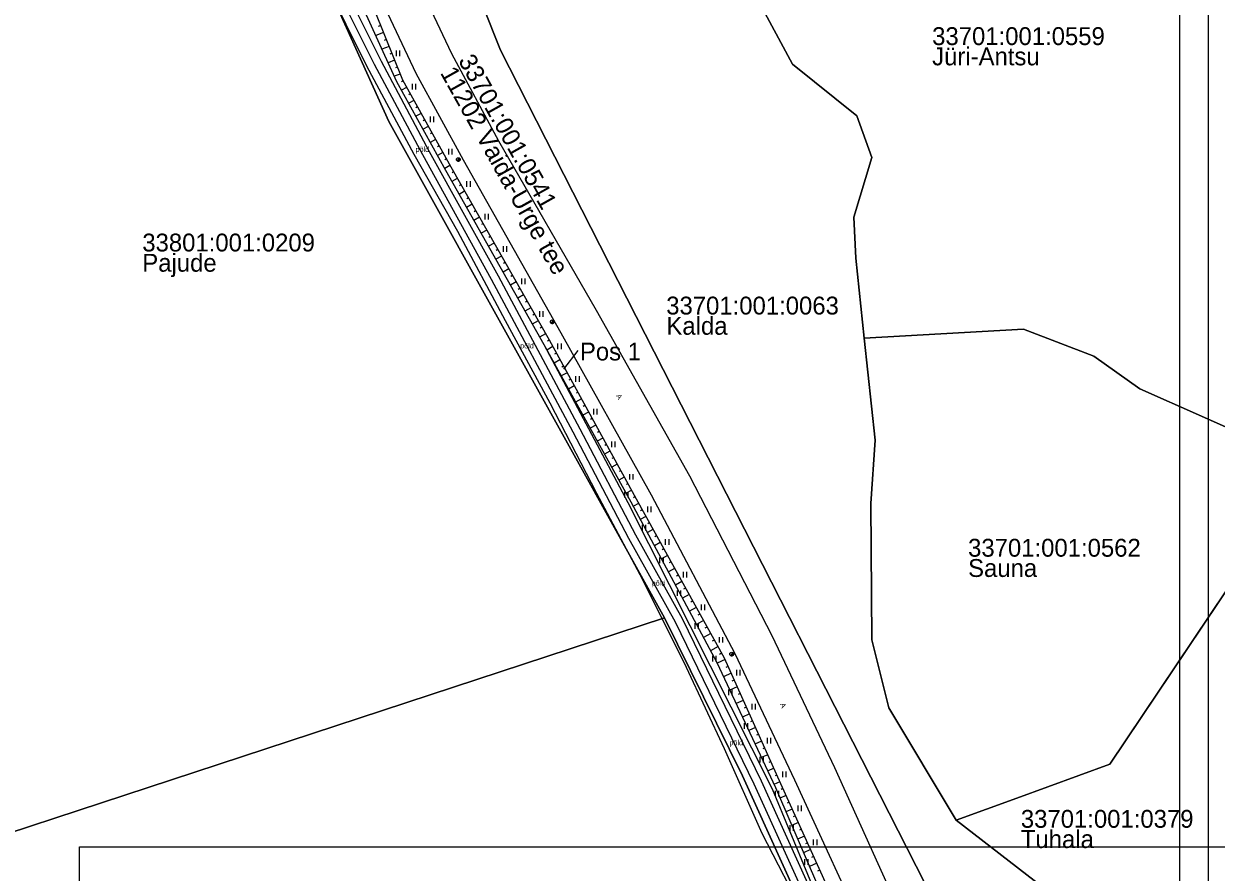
# Model space of a CAD drawing. Extents: x 554947 to 555436, y 6564938 to 6565792.
# Drawn here: x 555027.7 to 555187.9, y 6565441.5 to 6565555.5 of the extents above; entities that cross this region are included whole.
import ezdxf

# ---------------------------------------------------------------- set-up
doc = ezdxf.new("R2010")
doc.units = 0
for name, color, linetype in [('HALJASTUS', 7, 'Continuous'), ('KASUTUSALA', 7, 'Continuous'), ('KPKAABEL', 7, 'Continuous'), ('PIIR', 7, 'Continuous'), ('POST', 7, 'Continuous'), ('PR_SIDE', 7, 'Continuous'), ('RELJEEF', 7, 'Continuous'), ('TEE', 7, 'Continuous'), ('VORMISTUS_1', 7, 'Continuous'), ('VORMISTUS_2', 7, 'Continuous'), ('VORMISTUS_3', 7, 'Continuous')]:
    doc.layers.add(name, color=color, linetype=linetype)

msp = doc.modelspace()

# ---------------------------------------------------------------- linework, layer by layer
at = {"layer": 'HALJASTUS'}
for p, q in [((555077.72, 6565551.92), (555077.72, 6565551.16)), ((555078.18, 6565551.92), (555078.18, 6565551.16)), ((555079.87, 6565547.41), (555079.87, 6565546.65)), ((555080.32, 6565547.41), (555080.32, 6565546.65)), ((555082.32, 6565543.05), (555082.32, 6565542.29)), ((555082.77, 6565543.05), (555082.77, 6565542.29)), ((555084.77, 6565538.69), (555084.77, 6565537.93)), ((555085.22, 6565538.69), (555085.22, 6565537.93)), ((555087.21, 6565534.33), (555087.21, 6565533.57)), ((555087.67, 6565534.33), (555087.67, 6565533.57)), ((555089.66, 6565529.97), (555089.66, 6565529.21)), ((555090.12, 6565529.97), (555090.12, 6565529.21)), ((555092.11, 6565525.61), (555092.11, 6565524.85)), ((555092.57, 6565525.61), (555092.57, 6565524.85)), ((555094.56, 6565521.25), (555094.56, 6565520.49)), ((555095.01, 6565521.25), (555095.01, 6565520.49)), ((555097.01, 6565516.89), (555097.01, 6565516.13)), ((555097.46, 6565516.89), (555097.46, 6565516.13)), ((555099.44, 6565512.53), (555099.44, 6565511.76)), ((555099.9, 6565512.53), (555099.9, 6565511.76)), ((555101.85, 6565508.14), (555101.85, 6565507.38)), ((555102.31, 6565508.14), (555102.31, 6565507.38)), ((555104.27, 6565503.76), (555104.27, 6565503)), ((555104.72, 6565503.76), (555104.72, 6565503)), ((555106.68, 6565499.38), (555106.68, 6565498.62)), ((555107.13, 6565499.38), (555107.13, 6565498.62)), ((555109.09, 6565495), (555109.09, 6565494.24)), ((555109.54, 6565495), (555109.54, 6565494.24)), ((555108.42, 6565492.59), (555108.42, 6565491.83)), ((555108.87, 6565492.59), (555108.87, 6565491.83)), ((555111.5, 6565490.62), (555111.5, 6565489.86)), ((555111.95, 6565490.62), (555111.95, 6565489.86)), ((555110.78, 6565488.19), (555110.78, 6565487.43)), ((555111.24, 6565488.19), (555111.24, 6565487.43)), ((555113.91, 6565486.24), (555113.91, 6565485.48)), ((555114.36, 6565486.24), (555114.36, 6565485.48)), ((555113.14, 6565483.78), (555113.14, 6565483.02)), ((555113.6, 6565483.78), (555113.6, 6565483.02)), ((555116.32, 6565481.86), (555116.32, 6565481.1)), ((555116.77, 6565481.86), (555116.77, 6565481.1)), ((555115.51, 6565479.37), (555115.51, 6565478.61)), ((555115.96, 6565479.37), (555115.96, 6565478.61)), ((555118.73, 6565477.48), (555118.73, 6565476.72)), ((555119.18, 6565477.48), (555119.18, 6565476.72)), ((555117.87, 6565474.97), (555117.87, 6565474.21)), ((555118.32, 6565474.97), (555118.32, 6565474.21)), ((555121.14, 6565473.1), (555121.14, 6565472.34)), ((555121.6, 6565473.1), (555121.6, 6565472.34)), ((555120.23, 6565470.56), (555120.23, 6565469.8)), ((555120.69, 6565470.56), (555120.69, 6565469.8)), ((555123.46, 6565468.68), (555123.46, 6565467.92)), ((555123.92, 6565468.68), (555123.92, 6565467.92)), ((555122.38, 6565466.05), (555122.38, 6565465.28)), ((555122.83, 6565466.05), (555122.83, 6565465.28)), ((555125.53, 6565464.12), (555125.53, 6565463.36)), ((555125.98, 6565464.12), (555125.98, 6565463.36)), ((555124.5, 6565461.52), (555124.5, 6565460.76)), ((555124.95, 6565461.52), (555124.95, 6565460.76)), ((555127.59, 6565459.57), (555127.59, 6565458.81)), ((555128.05, 6565459.57), (555128.05, 6565458.81)), ((555126.61, 6565456.99), (555126.61, 6565456.23)), ((555127.07, 6565456.99), (555127.07, 6565456.23)), ((555129.66, 6565455.02), (555129.66, 6565454.26)), ((555130.12, 6565455.02), (555130.12, 6565454.26)), ((555128.68, 6565452.44), (555128.68, 6565451.67)), ((555129.14, 6565452.44), (555129.14, 6565451.67)), ((555131.73, 6565450.46), (555131.73, 6565449.7)), ((555132.18, 6565450.46), (555132.18, 6565449.7)), ((555130.64, 6565447.83), (555130.64, 6565447.07)), ((555131.09, 6565447.83), (555131.09, 6565447.07)), ((555133.79, 6565445.91), (555133.79, 6565445.15)), ((555134.25, 6565445.91), (555134.25, 6565445.15)), ((555132.6, 6565443.23), (555132.6, 6565442.47)), ((555133.05, 6565443.23), (555133.05, 6565442.47))]:
    msp.add_line(p, q, dxfattribs=at)
msp.add_lwpolyline([(555097.58, 6565512.39), (555108.86, 6565491.15), (555128.28, 6565452.72), (555137.76, 6565429.75), (555137.45, 6565422.91)], dxfattribs=at)
at = {"layer": 'KASUTUSALA'}
msp.add_lwpolyline([(555144.16, 6565410.6), (555124.27, 6565454.45), (555113.82, 6565475.68), (555076.76, 6565542.38), (555065.78, 6565566.7), (555060.42, 6565583.26), (555057.95, 6565596.72), (555059.66, 6565595.65), (555060.33, 6565594.85), (555062.36, 6565583.75), (555067.55, 6565567.72), (555071.2, 6565559.54), (555075.7, 6565550.48), (555082.19, 6565538.35), (555091.44, 6565521.62), (555102.43, 6565501.09), (555109.9, 6565486.83), (555116.17, 6565475.57), (555126.77, 6565453.77), (555135.2, 6565435.2)], dxfattribs=at)
at = {"layer": 'KPKAABEL'}
msp.add_lwpolyline([(555022.08, 6565654.91), (555021.62, 6565652.63), (555021.53, 6565649.77), (555022.79, 6565647.23), (555026.48, 6565641.46), (555030.61, 6565629.73), (555035.38, 6565618.81), (555040.84, 6565608.06), (555047.09, 6565597.8), (555053.57, 6565587.29), (555056.07, 6565583.7), (555062.11, 6565572.67), (555068.25, 6565560.98), (555073.77, 6565549.85), (555080.11, 6565537.98), (555085.96, 6565527.61), (555092.4, 6565515.61), (555098.4, 6565504.54), (555104.64, 6565492.44), (555110.84, 6565480.82), (555116.7, 6565469.07), (555121.82, 6565458.12), (555126.89, 6565446.73), (555132.74, 6565435.39)], dxfattribs=at)
at = {"layer": 'PIIR'}
for points in [[(555016.05, 6565654.91), (555030.24, 6565648.23), (555043.11, 6565640.11), (555053.62, 6565632.14), (555056.61, 6565622.91), (555057.22, 6565600.73), (555060.42, 6565583.26), (555065.78, 6565566.7), (555076.76, 6565542.38), (555113.82, 6565475.68), (554946.63, 6565420.78), (554981.01, 6565316.76), (555160.07, 6565375.54), (555166.64, 6565360.5), (555167.67, 6565357.91)], [(555144.16, 6565410.6), (555124.27, 6565454.45), (555113.82, 6565475.68), (555076.76, 6565542.38), (555065.78, 6565566.7), (555060.42, 6565583.26), (555057.22, 6565600.73), (555056.61, 6565622.91), (555063.43, 6565647.29), (555114.24, 6565634), (555129.77, 6565611.2), (555130.73, 6565621.32), (555138.66, 6565615.26), (555160.12, 6565598.86), (555193.24, 6565604.68), (555193.7, 6565602.7), (555225.47, 6565605.89), (555234.35, 6565605.6), (555251.24, 6565598.48), (555330.71, 6565538.85), (555343.81, 6565536.56), (555350.68, 6565540.44), (555361.56, 6565549.57), (555393.07, 6565582.1)], [(555171.91, 6565394.64), (555091.74, 6565551.94), (555075.34, 6565593.24), (555074.13, 6565607.82), (555079.04, 6565618.4), (555093.56, 6565628.47), (555109.96, 6565624.83), (555116.17, 6565610.5), (555099.5, 6565594.91), (555105.26, 6565587.71), (555119.63, 6565564.84), (555126.35, 6565558.74), (555131.01, 6565550.06), (555139.64, 6565543.1), (555141.68, 6565537.52), (555139.26, 6565529.51), (555139.49, 6565523.98), (555140.65, 6565513.25), (555142.13, 6565499.56), (555141.53, 6565491.02), (555141.65, 6565472.71), (555143.93, 6565463.6), (555153.01, 6565448.47), (555207.22, 6565406.57)], [(555393.07, 6565560.97), (555353.12, 6565523.87), (555343.14, 6565512.46), (555302.6, 6565539.71), (555242.37, 6565583.94), (555179.42, 6565586.32), (555138.98, 6565580.6), (555121.18, 6565602.26), (555116.17, 6565610.5), (555109.96, 6565624.83), (555093.56, 6565628.47), (555079.04, 6565618.4), (555074.13, 6565607.82), (555075.34, 6565593.24), (555091.74, 6565551.94), (555171.91, 6565394.64), (555191.35, 6565341.19), (555195.08, 6565294.61), (555195.28, 6565271.63), (555191.64, 6565237.48)]]:
    msp.add_lwpolyline(points, dxfattribs=at)
for points in [[(555121.18, 6565602.26), (555138.98, 6565580.6), (555179.42, 6565586.32), (555242.37, 6565583.94), (555302.6, 6565539.71), (555287.77, 6565518.56), (555207.29, 6565506.14), (555200.64, 6565496.23), (555185.97, 6565502.75), (555177.68, 6565506.44), (555171.49, 6565510.85), (555162.05, 6565514.45), (555140.65, 6565513.25), (555139.49, 6565523.98), (555139.26, 6565529.51), (555141.68, 6565537.52), (555139.64, 6565543.1), (555131.01, 6565550.06), (555126.35, 6565558.74), (555119.63, 6565564.84), (555105.26, 6565587.71), (555099.5, 6565594.91), (555116.17, 6565610.5)], [(555153.01, 6565448.47), (555161.15, 6565451.45), (555173.66, 6565456.03), (555207.29, 6565506.14), (555287.77, 6565518.56), (555302.6, 6565539.71), (555343.14, 6565512.46), (555319.44, 6565481.04), (555323.07, 6565461.26), (555312.9, 6565433.84), (555316.84, 6565372.52), (555318.72, 6565342.57), (555320.51, 6565314.61), (555303.13, 6565302.54), (555208.78, 6565303.3), (555205.15, 6565297.11), (555200.72, 6565310.3), (555206.9, 6565339.44), (555221.23, 6565376.06), (555216.83, 6565392.35), (555207.22, 6565406.57)], [(555140.65, 6565513.25), (555162.05, 6565514.45), (555171.49, 6565510.85), (555177.68, 6565506.44), (555185.97, 6565502.75), (555200.64, 6565496.23), (555173.66, 6565456.03), (555161.15, 6565451.45), (555153.01, 6565448.47), (555143.93, 6565463.6), (555141.65, 6565472.71), (555141.53, 6565491.02), (555142.13, 6565499.56)], [(554981.01, 6565316.76), (554946.63, 6565420.78), (555113.82, 6565475.68), (555124.27, 6565454.45), (555144.16, 6565410.6), (555160.07, 6565375.54)]]:
    msp.add_lwpolyline(points, close=True, dxfattribs=at)
at = {"layer": 'POST'}
for p, q in [((555085.91, 6565537.07), (555086.26, 6565537.43)), ((555098.55, 6565515.27), (555098.9, 6565515.62)), ((555122.66, 6565470.63), (555123.01, 6565470.98))]:
    msp.add_line(p, q, dxfattribs=at)
for centre in [(555086.09, 6565537.25), (555098.72, 6565515.45), (555122.83, 6565470.81)]:
    msp.add_circle(centre, 0.25, dxfattribs=at)
for centre, radius, start, end in [((555086.09, 6565537.25), 0.225, 224.8541, 45.0356), ((555086.09, 6565537.25), 0.2, 224.8427, 45.047), ((555086.09, 6565537.25), 0.175, 224.8281, 45.0616), ((555086.09, 6565537.25), 0.15, 224.8087, 45.081), ((555086.09, 6565537.25), 0.125, 224.7814, 45.1083), ((555086.09, 6565537.25), 0.1, 224.7406, 45.1491), ((555086.09, 6565537.25), 0.075, 224.6725, 45.2172), ((555086.09, 6565537.25), 0.05, 224.5363, 45.3534), ((555086.09, 6565537.25), 0.025, 224.1278, 45.7619), ((555098.72, 6565515.45), 0.225, 224.8541, 45.0356), ((555098.72, 6565515.45), 0.2, 224.8427, 45.047), ((555098.72, 6565515.45), 0.175, 224.8281, 45.0616), ((555098.72, 6565515.45), 0.15, 224.8087, 45.081), ((555098.72, 6565515.45), 0.125, 224.7814, 45.1083), ((555098.72, 6565515.45), 0.1, 224.7406, 45.1491), ((555098.72, 6565515.45), 0.075, 224.6725, 45.2172), ((555098.72, 6565515.45), 0.05, 224.5363, 45.3534), ((555098.72, 6565515.45), 0.025, 224.1278, 45.7619), ((555122.83, 6565470.81), 0.225, 224.8541, 45.0356), ((555122.83, 6565470.81), 0.2, 224.8427, 45.047), ((555122.83, 6565470.81), 0.175, 224.8281, 45.0616), ((555122.83, 6565470.81), 0.15, 224.8087, 45.081), ((555122.83, 6565470.81), 0.125, 224.7814, 45.1083), ((555122.83, 6565470.81), 0.1, 224.7406, 45.1491), ((555122.83, 6565470.81), 0.075, 224.6725, 45.2172), ((555122.83, 6565470.81), 0.05, 224.5363, 45.3534), ((555122.83, 6565470.81), 0.025, 224.1278, 45.7619)]:
    msp.add_arc(centre, radius, start, end, dxfattribs=at)
at = {"layer": 'PR_SIDE'}
msp.add_lwpolyline([(555134.29, 6565434.78), (555125.87, 6565453.35), (555115.28, 6565475.11), (555109.02, 6565486.35), (555101.54, 6565500.63), (555090.56, 6565521.15), (555081.31, 6565537.88), (555074.81, 6565550.02), (555070.29, 6565559.11)], dxfattribs=at)
at = {"layer": 'RELJEEF'}
for p, q in [((555076.04, 6565554.31), (555075, 6565553.9)), ((555075.66, 6565555.24), (555075.34, 6565555.11)), ((555076.41, 6565553.38), (555076.11, 6565553.26)), ((555076.78, 6565552.45), (555075.83, 6565552.08)), ((555077.15, 6565551.53), (555076.88, 6565551.42)), ((555077.52, 6565550.6), (555076.66, 6565550.25)), ((555077.89, 6565549.67), (555077.65, 6565549.57)), ((555078.27, 6565548.74), (555077.49, 6565548.43)), ((555078.66, 6565547.82), (555078.45, 6565547.71)), ((555079.14, 6565546.95), (555078.45, 6565546.57)), ((555079.63, 6565546.07), (555079.42, 6565545.96)), ((555080.11, 6565545.2), (555079.42, 6565544.81)), ((555080.6, 6565544.33), (555080.39, 6565544.21)), ((555081.08, 6565543.45), (555080.39, 6565543.06)), ((555082.05, 6565541.7), (555081.35, 6565541.31)), ((555081.57, 6565542.58), (555081.36, 6565542.46)), ((555083.02, 6565539.95), (555082.32, 6565539.56)), ((555082.54, 6565540.83), (555082.33, 6565540.71)), ((555083.51, 6565539.08), (555083.3, 6565538.96)), ((555084, 6565538.2), (555083.29, 6565537.81)), ((555084.48, 6565537.33), (555084.27, 6565537.21)), ((555084.97, 6565536.46), (555084.26, 6565536.06)), ((555085.46, 6565535.59), (555085.25, 6565535.46)), ((555085.95, 6565534.72), (555085.24, 6565534.31)), ((555086.45, 6565533.85), (555086.23, 6565533.72)), ((555086.94, 6565532.98), (555086.22, 6565532.57)), ((555087.44, 6565532.11), (555087.22, 6565531.98)), ((555087.93, 6565531.24), (555087.2, 6565530.82)), ((555088.42, 6565530.37), (555088.2, 6565530.24)), ((555088.92, 6565529.5), (555088.18, 6565529.08)), ((555089.91, 6565527.76), (555089.16, 6565527.34)), ((555089.41, 6565528.63), (555089.19, 6565528.51)), ((555090.9, 6565526.02), (555090.14, 6565525.6)), ((555090.4, 6565526.89), (555090.18, 6565526.77)), ((555091.88, 6565524.29), (555091.13, 6565523.85)), ((555091.39, 6565525.15), (555091.16, 6565525.03)), ((555092.87, 6565522.55), (555092.11, 6565522.11)), ((555092.38, 6565523.42), (555092.15, 6565523.29)), ((555093.86, 6565520.81), (555093.09, 6565520.37)), ((555093.37, 6565521.68), (555093.14, 6565521.55)), ((555094.85, 6565519.07), (555094.07, 6565518.62)), ((555094.36, 6565519.94), (555094.12, 6565519.81)), ((555095.35, 6565518.2), (555095.11, 6565518.07)), ((555095.84, 6565517.33), (555095.05, 6565516.88)), ((555096.33, 6565516.46), (555096.1, 6565516.33)), ((555096.83, 6565515.59), (555096.03, 6565515.14)), ((555097.32, 6565514.72), (555097.08, 6565514.59)), ((555097.82, 6565513.85), (555097.01, 6565513.4)), ((555098.31, 6565512.98), (555098.07, 6565512.85)), ((555098.79, 6565512.11), (555097.98, 6565511.66)), ((555099.27, 6565511.23), (555099.03, 6565511.1)), ((555099.75, 6565510.35), (555098.95, 6565509.91)), ((555100.23, 6565509.47), (555099.99, 6565509.34)), ((555100.71, 6565508.6), (555099.92, 6565508.17)), ((555101.67, 6565506.84), (555100.89, 6565506.42)), ((555101.19, 6565507.72), (555100.95, 6565507.59)), ((555102.63, 6565505.09), (555101.86, 6565504.67)), ((555102.15, 6565505.96), (555101.92, 6565505.84)), ((555103.59, 6565503.33), (555102.83, 6565502.92)), ((555103.11, 6565504.21), (555102.88, 6565504.08)), ((555104.55, 6565501.58), (555103.8, 6565501.17)), ((555104.07, 6565502.46), (555103.84, 6565502.33)), ((555105.51, 6565499.82), (555104.77, 6565499.42)), ((555105.03, 6565500.7), (555104.8, 6565500.58)), ((555105.99, 6565498.95), (555105.77, 6565498.83)), ((555106.47, 6565498.07), (555105.74, 6565497.67)), ((555106.95, 6565497.19), (555106.73, 6565497.07)), ((555107.43, 6565496.31), (555106.71, 6565495.92)), ((555107.91, 6565495.44), (555107.69, 6565495.32)), ((555108.38, 6565494.56), (555107.68, 6565494.17)), ((555108.86, 6565493.68), (555108.65, 6565493.57)), ((555109.34, 6565492.8), (555108.65, 6565492.42)), ((555109.82, 6565491.93), (555109.62, 6565491.81)), ((555110.31, 6565491.05), (555109.61, 6565490.66)), ((555111.28, 6565489.3), (555110.55, 6565488.9)), ((555110.79, 6565490.18), (555110.58, 6565490.06)), ((555112.25, 6565487.55), (555111.5, 6565487.14)), ((555111.76, 6565488.43), (555111.54, 6565488.3)), ((555113.22, 6565485.81), (555112.44, 6565485.37)), ((555112.73, 6565486.68), (555112.5, 6565486.55)), ((555114.19, 6565484.06), (555113.38, 6565483.61)), ((555113.71, 6565484.93), (555113.47, 6565484.8)), ((555115.16, 6565482.31), (555114.33, 6565481.84)), ((555114.68, 6565483.18), (555114.43, 6565483.05)), ((555115.65, 6565481.43), (555115.39, 6565481.29)), ((555116.13, 6565480.56), (555115.27, 6565480.08)), ((555116.62, 6565479.68), (555116.35, 6565479.54)), ((555117.1, 6565478.81), (555116.21, 6565478.32)), ((555117.59, 6565477.94), (555117.32, 6565477.79)), ((555118.07, 6565477.06), (555117.15, 6565476.55)), ((555118.56, 6565476.19), (555118.28, 6565476.03)), ((555119.04, 6565475.31), (555118.1, 6565474.79)), ((555119.53, 6565474.44), (555119.24, 6565474.28)), ((555120.02, 6565473.56), (555119.04, 6565473.02)), ((555120.5, 6565472.69), (555120.2, 6565472.53)), ((555120.99, 6565471.82), (555119.98, 6565471.26)), ((555121.93, 6565470.06), (555120.87, 6565469.58)), ((555121.47, 6565470.94), (555121.17, 6565470.77)), ((555122.75, 6565468.23), (555121.72, 6565467.77)), ((555122.34, 6565469.14), (555122.03, 6565469)), ((555123.57, 6565466.41), (555122.57, 6565465.96)), ((555123.16, 6565467.32), (555122.86, 6565467.18)), ((555124.39, 6565464.58), (555123.42, 6565464.15)), ((555123.98, 6565465.5), (555123.69, 6565465.36)), ((555124.8, 6565463.67), (555124.52, 6565463.54)), ((555125.21, 6565462.76), (555124.27, 6565462.33)), ((555125.62, 6565461.85), (555125.34, 6565461.72)), ((555126.03, 6565460.94), (555125.11, 6565460.52)), ((555126.44, 6565460.02), (555126.17, 6565459.9)), ((555126.85, 6565459.11), (555125.96, 6565458.71)), ((555127.26, 6565458.2), (555127, 6565458.08)), ((555127.67, 6565457.29), (555126.81, 6565456.9)), ((555128.49, 6565455.46), (555127.66, 6565455.09)), ((555128.08, 6565456.37), (555127.83, 6565456.26)), ((555129.31, 6565453.64), (555128.51, 6565453.28)), ((555128.9, 6565454.55), (555128.66, 6565454.44)), ((555130.14, 6565451.82), (555129.31, 6565451.44)), ((555129.72, 6565452.73), (555129.48, 6565452.62)), ((555130.55, 6565450.9), (555130.3, 6565450.79)), ((555130.96, 6565449.99), (555130.1, 6565449.61)), ((555131.37, 6565449.08), (555131.11, 6565448.96)), ((555131.78, 6565448.17), (555130.9, 6565447.77)), ((555132.2, 6565447.26), (555131.92, 6565447.14)), ((555132.61, 6565446.35), (555131.69, 6565445.93)), ((555133.02, 6565445.44), (555132.74, 6565445.31)), ((555133.43, 6565444.53), (555132.48, 6565444.09)), ((555134.26, 6565442.7), (555133.27, 6565442.26)), ((555133.84, 6565443.62), (555133.55, 6565443.48)), ((555134.67, 6565441.79), (555134.37, 6565441.66))]:
    msp.add_line(p, q, dxfattribs=at)
for points in [[(555061.19, 6565603.86), (555063.02, 6565596.51), (555064.38, 6565585.09), (555067.44, 6565575.67), (555073.66, 6565560.25), (555078.57, 6565547.98), (555085.07, 6565536.27), (555098.29, 6565513.03), (555109.98, 6565491.65), (555121.81, 6565470.32), (555129.41, 6565453.42), (555139.71, 6565430.65), (555142.38, 6565424.28), (555142.55, 6565422.18)], [(555061.19, 6565603.86), (555061.85, 6565596.37), (555062.87, 6565584.51), (555066.18, 6565575.08), (555072.1, 6565560.27), (555077.8, 6565547.74), (555084.38, 6565535.83), (555097.58, 6565512.39), (555109.29, 6565491.27), (555120.83, 6565469.69), (555128.7, 6565452.87), (555138.48, 6565430.17), (555141.35, 6565423.96), (555142.55, 6565422.18)]]:
    msp.add_lwpolyline(points, dxfattribs=at)
at = {"layer": 'TEE'}
for points in [[(555063.04, 6565604.03), (555063.89, 6565596.59), (555066.15, 6565585.55), (555068.84, 6565576.18), (555074.68, 6565560.94), (555080.39, 6565548.87), (555086.72, 6565537.19), (555099.86, 6565513.95), (555112, 6565492.2), (555123.27, 6565470.87), (555131.27, 6565453.89), (555141.63, 6565431.43)], [(555146.7, 6565433.42), (555136.69, 6565455.53), (555128.27, 6565473.28), (555117.19, 6565494.73), (555104.65, 6565516.95), (555091.54, 6565539.74), (555085.22, 6565551.47), (555079.65, 6565563.24), (555074, 6565577.71), (555071.34, 6565586.86), (555069.39, 6565597.54), (555068.63, 6565604.43)]]:
    msp.add_lwpolyline(points, dxfattribs=at)
at = {"layer": 'VORMISTUS_1'}
msp.add_lwpolyline([(555035.19, 6565444.91), (555245.19, 6565444.91), (555245.19, 6565147.91), (555035.19, 6565147.91)], close=True, dxfattribs=at)
at = {"layer": 'VORMISTUS_2'}
msp.add_line((555100.25, 6565509.08), (555102.2, 6565511.58), dxfattribs=at)
msp.add_lwpolyline([(555186.86, 6565394.91), (555021.86, 6565394.91), (555021.86, 6565604.91), (555186.86, 6565604.91)], close=True, dxfattribs=at)
at = {"layer": 'VORMISTUS_3'}
msp.add_lwpolyline([(555183.07, 6565701.75), (555393.07, 6565701.75), (555393.07, 6565404.75), (555183.07, 6565404.75)], close=True, dxfattribs=at)

# ---------------------------------------------------------------- texts
at = {"layer": 'HALJASTUS'}
for p in [(555080.34, 6565538.27), (555094.4, 6565511.88), (555112.08, 6565479.98), (555122.52, 6565458.55)]:
    msp.add_text('põld', height=0.7, rotation=359.9544, dxfattribs=at).set_placement(p)
at = {"layer": 'PIIR'}
for s, p in [('33701:001:0559', (555149.77, 6565552.63)), ('Jüri-Antsu', (555149.77, 6565549.91)), ('33801:001:0209', (555043.62, 6565524.9)), ('Pajude', (555043.62, 6565522.18)), ('33701:001:0063', (555114.03, 6565516.43)), ('Kalda', (555114.06, 6565513.71)), ('33701:001:0562', (555154.6, 6565483.89)), ('Sauna', (555154.6, 6565481.17)), ('33701:001:0379', (555161.69, 6565447.47)), ('Tuhala', (555161.69, 6565444.75))]:
    msp.add_text(s, height=2.4, dxfattribs=at).set_placement(p)
for s, p in [('33701:001:0541', (555086.02, 6565550.55)), ('11202 Vaida-Urge tee', (555083.6, 6565548.9))]:
    msp.add_text(s, height=2.4, rotation=299.2738, dxfattribs=at).set_placement(p)
at = {"layer": 'TEE'}
for rotation, p in [(299.9634, (555107.26, 6565505.5)), (292.7913, (555129.3, 6565464.07))]:
    msp.add_text('A', height=0.7, rotation=rotation, dxfattribs=at).set_placement(p)
at = {"layer": 'VORMISTUS_2'}
msp.add_text('Pos 1', height=2.4, dxfattribs=at).set_placement((555102.43, 6565510.26))

doc.saveas('drawing.dxf')
